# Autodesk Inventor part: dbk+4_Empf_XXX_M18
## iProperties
Shininess: 20.0
Length Units: 11269
Angle Units: 11279
Time Units: 11290
Mass Units: 11283
Length Display Precision: 2
Angle Display Precision: 2
Part Number: dbk+4_Empf_XXX_M18
Material: Nichtrostender Stahl - 440C
Document SubType Name: Modellieren
Description: Ipc-25 /CXX/M18
Checked By: Alves
Created: 2005-08
Designer: Ohle
Manufacturer: Standard
Standards Organization: Custom
Density: 0.0
Volumn: 0.0
Area: 0.0
PropertySet Name: Model Information
Control State: 0
Master: False
Checked Out: False
BESTELLNUMMER: Ipc-25 /CXX/M18
ME: ST
Title: Ipc Sensoren
Author: Ohle
Comments: keine Bemerkung
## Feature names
1. Grundkörper [Revolution]
2. Flächenverjüngung1
3. Extrusion10
4. Rundung3 [Fillet]
5. Extrusion11
6. Kabelauslass [Extrusion]
